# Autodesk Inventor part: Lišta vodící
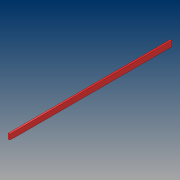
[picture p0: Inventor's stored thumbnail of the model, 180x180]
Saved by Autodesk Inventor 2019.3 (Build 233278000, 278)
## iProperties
Created: 2019-03
Part Number: Lišta vodící
Material: Ocel, měkká, svařovaná
Document SubType Name: Modeling
Designer: B-hon
Density: 7.85 g/cm^3
Appearance: Světle červená
Author: B-hon
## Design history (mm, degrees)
sketch "Náčrt1"
  geometry: L1 (0, 0)-(5, 0); L2 (5, 0)-(5, 20); L3 (5, 20)-(0, 20); L4 (0, 20)-(0, 0)
  constraints: 8 end point, 2 parallel, 1 horizontal, 1 perpendicular
  dimensions: "d0" = 5 distance of L3.end L2.end; "d1" = 20 distance of L2.end L1.end
extrude "Vysunutí1" new body sketch "Náčrt1" distance "d2" = 555; taper "d3" = 0 deg
chamfer "Zkosení2" distance "d7" = 1.5; stored, may be unused: second distance "d8" = 2, angle "d9" = 85 deg
node "Upravit přímo1"
node "Těleso1"
feature "Posunout1" dims "d16" = 28.6
other parameters: "d14" = 0, "d15" = 0
